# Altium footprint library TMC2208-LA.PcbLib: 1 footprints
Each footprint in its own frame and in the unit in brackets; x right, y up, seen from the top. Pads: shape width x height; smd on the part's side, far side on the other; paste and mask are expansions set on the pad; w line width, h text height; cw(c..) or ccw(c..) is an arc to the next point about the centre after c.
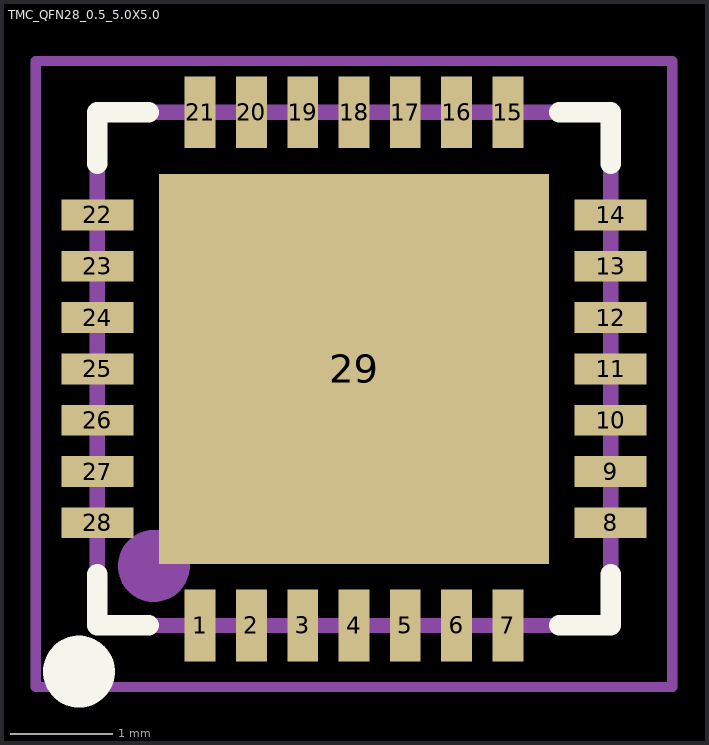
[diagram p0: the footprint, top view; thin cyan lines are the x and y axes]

## TMC_QFN28_0.5_5.0X5.0 [mm]
height 0.9
pads (29):
  rect 0.3x0.7 smd: 1(-1017.5,-1018.5) 2(-1017,-1018.5) 3(-1016.5,-1018.5) 4(-1016,-1018.5) 5(-1015.5,-1018.5) 6(-1015,-1018.5) 7(-1014.5,-1018.5) 15(-1014.5,-1013.5) 16(-1015,-1013.5) 17(-1015.5,-1013.5) 18(-1016,-1013.5) 19(-1016.5,-1013.5) 20(-1017,-1013.5) 21(-1017.5,-1013.5)
  rect 0.7x0.3 smd: 8(-1013.5,-1017.5) 9(-1013.5,-1017) 10(-1013.5,-1016.5) 11(-1013.5,-1016) 12(-1013.5,-1015.5) 13(-1013.5,-1015) 14(-1013.5,-1014.5) 22(-1018.5,-1014.5) 23(-1018.5,-1015) 24(-1018.5,-1015.5) 25(-1018.5,-1016) 26(-1018.5,-1016.5) 27(-1018.5,-1017) 28(-1018.5,-1017.5)
  rect 3.8x3.8 smd paste-25.4: 29(-1016,-1016)
Top Overlay:
  circle w0.5: c-1018.68,-1018.95 r0.1
  lines w0.2: -1018.5,-1018 -1018.5,-1018.5 -1018,-1018.5 ; -1018.5,-1014 -1018.5,-1013.5 -1018,-1013.5 ; -1014,-1018.5 -1013.5,-1018.5 -1013.5,-1018 ; -1014,-1013.5 -1013.5,-1013.5 -1013.5,-1014
Top Paste:
  region: -1017.59,-1014.37 -1016.29,-1014.37 -1016.29,-1015.72 -1017.59,-1015.72
  region: -1015.69,-1015.7 -1014.39,-1015.7 -1014.39,-1014.35 -1015.69,-1014.35
  region: -1015.69,-1016.3 -1014.39,-1016.3 -1014.39,-1017.6 -1015.69,-1017.6
  region: -1017.56,-1016.25 -1016.26,-1016.25 -1016.26,-1017.6 -1017.56,-1017.6
Mechanical 1:
  circle w0.5: c-1017.95,-1017.92 r0.1
  lines w0.15: -1018.5,-1018.5 -1013.5,-1018.5 -1013.5,-1013.5 -1018.5,-1013.5 -1018.5,-1018.5
  text "IC1" at -1016.56,-1016.427 h0.6
Mechanical 16:
  lines w0.1: -1019.1,-1019.1 -1012.9,-1019.1 -1012.9,-1013 -1019.1,-1013 -1019.1,-1019.1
